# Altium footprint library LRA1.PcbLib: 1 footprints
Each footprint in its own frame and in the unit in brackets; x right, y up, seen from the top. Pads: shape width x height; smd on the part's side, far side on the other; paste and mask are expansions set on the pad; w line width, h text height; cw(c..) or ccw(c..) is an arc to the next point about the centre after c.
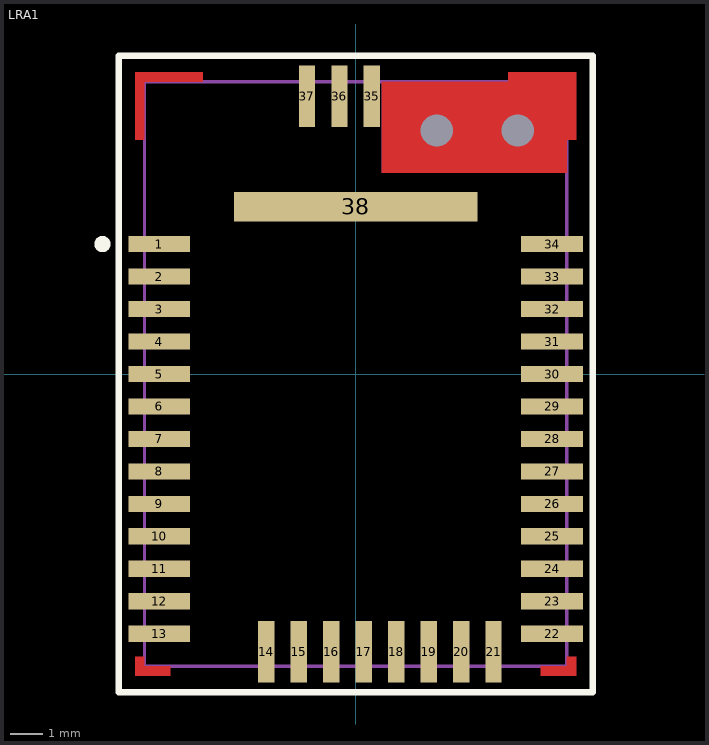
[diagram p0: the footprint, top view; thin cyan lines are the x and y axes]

## LRA1 [mm]
pads (40):
  rect 1.9x0.5 smd mask+0.1: 1(-6.05,4) 2(-6.05,3) 3(-6.05,2) 4(-6.05,1) 5(-6.05,0) 6(-6.05,-1) 7(-6.05,-2) 8(-6.05,-3) 9(-6.05,-4) 10(-6.05,-5) 11(-6.05,-6) 12(-6.05,-7) 13(-6.05,-8) 22(6.05,-8) 23(6.05,-7) 24(6.05,-6) 25(6.05,-5) 26(6.05,-4) 27(6.05,-3) 28(6.05,-2) 29(6.05,-1) 30(6.05,0) 31(6.05,1) 32(6.05,2) 33(6.05,3) 34(6.05,4)
  rect 0.5x1.9 smd mask+0.1: 14(-2.75,-8.55) 15(-1.75,-8.55) 16(-0.75,-8.55) 17(0.25,-8.55) 18(1.25,-8.55) 19(2.25,-8.55) 20(3.25,-8.55) 21(4.25,-8.55) 35(0.5,8.55) 36(-0.5,8.55) 37(-1.5,8.55)
  rect 7.5x0.9 smd paste-0.5 mask+0.05: 38(0,5.15)
  round 0.2 hole 1 unplated mask+0.15: 100(2.5,7.5) 101(5,7.5)
Top Layer:
  rectangle: -6.8,-9.3 -6.5,-8.7
  rectangle: 4.7,9 6.8,9.3
  region: 6.8,7.2 6.8,9.3 6.5,9.3 6.5,7.2
  region: 6.5,-8.7 6.5,-9.3 6.8,-9.3 6.8,-8.7
  region: -4.7,9.3 -6.8,9.3 -6.8,9 -4.7,9
  region: -6.5,7.2 -6.5,9.3 -6.8,9.3 -6.8,7.2
  region: -5.7,-9 -6.8,-9 -6.8,-9.3 -5.7,-9.3
  region: 6.8,-9 5.7,-9 5.7,-9.3 6.8,-9.3
  pour cut-out: 6.5,9 0.8,9 0.8,6.2 6.5,6.2
Bottom Layer:
  pour cut-out: 0.8,9 0.8,6.2 6.5,6.2 6.5,9
Top Overlay:
  circle w0.3: c-7.8,4 r0.1
  lines w0.2: -7.3,-9.8 7.3,-9.8 7.3,9.8 -7.3,9.8 -7.3,-9.8
Top Paste:
  rectangle: 2.25,4.7 2.75,5.6
  rectangle: 3.25,4.7 3.75,5.6
  rectangle: 0.25,4.7 0.75,5.6
  rectangle: 1.25,4.7 1.75,5.6
  rectangle: -1.75,4.7 -1.25,5.6
  rectangle: -0.75,4.7 -0.25,5.6
  rectangle: -2.75,4.7 -2.25,5.6
  rectangle: -3.75,4.7 -3.25,5.6
Top Solder:
  rectangle: -6.9,-9.4 -6.4,-8.6
  rectangle: 4.6,8.9 6.9,9.4
  region: 6.9,7.1 6.9,9.4 6.4,9.4 6.4,7.1
  region: 6.4,-8.6 6.4,-9.4 6.9,-9.4 6.9,-8.6
  region: -4.6,9.4 -6.9,9.4 -6.9,8.9 -4.6,8.9
  region: -6.4,7.1 -6.4,9.4 -6.9,9.4 -6.9,7.1
  region: -5.6,-8.9 -6.9,-8.9 -6.9,-9.4 -5.6,-9.4
  region: 6.9,-8.9 5.6,-8.9 5.6,-9.4 6.9,-9.4
Top Assembly (Mech7):
  lines w0.1: -6.5,-9 -6.5,9 6.5,9 6.5,-9 -6.5,-9
  text ".Designator" at -0.5,0 h1.52
3D body "LRA1 v4.step": height 2.4, standoff -0.01, extent -6.5,-9 6.5,9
